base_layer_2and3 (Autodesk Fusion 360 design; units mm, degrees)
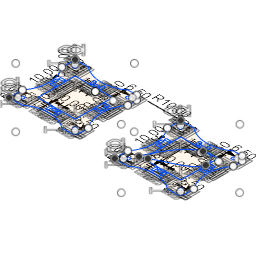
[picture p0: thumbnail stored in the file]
sketch "Sketch1" plane through (0, 0, 0) normal (0, 1, 0) x axis (1, 0, 0)
  line L1 (-53.5322, -77.3934) -> (31.4678, -77.3934)
  line L2 (-53.5322, 7.6066) -> (-53.5322, -77.3934)
  line L3 (31.4678, -77.3934) -> (31.4678, 7.6066)
  line L4 (37.4678, 2.6066) -> (40.4678, 2.6066)
  line L5 (63.9678, 9.8155) -> (63.9678, 30.1039)
  line L6 (-86.0322, -99.8934) -> (-86.0322, -79.8934)
  line L7 (63.9678, -79.8934) -> (63.9678, -99.8934)
  line L8 (53.9678, -109.8934) -> (33.9678, -109.8934)
  line L9 (-76.0322, -109.8934) -> (-56.0322, -109.8934)
  line L10 (-86.0322, 10.1066) -> (-86.0322, 30.1026)
  line L11 (53.9691, 40.1039) -> (33.9678, 40.1066)
  line L12 (-76.0322, 40.1026) -> (-56.0322, 40.1026)
  curve K1 (-62.3587, -78.4407) -> (-62.3587, -78.4407)
  line L13 (33.4678, -36.6974) -> (44.9678, -36.6974)
  line L14 (33.4678, -31.6974) -> (33.4678, -36.6974)
  line L15 (44.9678, -31.6974) -> (33.4678, -31.6974)
  line L16 (44.9678, -36.6974) -> (44.9678, -31.6974)
  line L17 (33.4678, -16.6974) -> (44.9678, -16.6974)
  line L18 (33.4678, -11.6974) -> (33.4678, -16.6974)
  line L19 (44.9678, -11.6974) -> (33.4678, -11.6974)
  line L20 (44.9678, -16.6974) -> (44.9678, -11.6974)
  line L21 (-2.5269, 20.8155) -> (2.4731, 20.8155)
  line L22 (-2.5269, 9.3155) -> (-2.5269, 20.8155)
  line L23 (2.4731, 9.3155) -> (-2.5269, 9.3155)
  line L24 (2.4731, 20.8155) -> (2.4731, 9.3155)
  line L25 (-22.5269, 20.8155) -> (-17.5269, 20.8155)
  line L26 (-22.5269, 9.3155) -> (-22.5269, 20.8155)
  line L27 (-17.5269, 9.3155) -> (-22.5269, 9.3155)
  line L28 (-17.5269, 20.8155) -> (-17.5269, 9.3155)
  line L29 (-55.5322, -11.6974) -> (-67.0322, -11.6974)
  line L30 (-55.5322, -16.6974) -> (-55.5322, -11.6974)
  line L31 (-67.0322, -16.6974) -> (-55.5322, -16.6974)
  line L32 (-67.0322, -11.6974) -> (-67.0322, -16.6974)
  line L33 (-55.5322, -31.6974) -> (-67.0322, -31.6974)
  line L34 (-55.5322, -36.6974) -> (-55.5322, -31.6974)
  line L35 (-67.0322, -36.6974) -> (-55.5322, -36.6974)
  line L36 (-67.0322, -31.6974) -> (-67.0322, -36.6974)
  line L37 (-17.5269, -90.8934) -> (-22.5269, -90.8934)
  line L38 (-17.5269, -79.3934) -> (-17.5269, -90.8934)
  line L39 (-22.5269, -79.3934) -> (-17.5269, -79.3934)
  line L40 (-22.5269, -90.8934) -> (-22.5269, -79.3934)
  line L41 (2.4731, -90.8934) -> (-2.5269, -90.8934)
  line L42 (2.4731, -79.3934) -> (2.4731, -90.8934)
  line L43 (-2.5269, -79.3934) -> (2.4731, -79.3934)
  line L44 (-2.5269, -90.8934) -> (-2.5269, -79.3934)
  line L45 (-53.5322, 7.6066) -> (31.4678, 7.6066)
  line L46 (45.4678, 22.1046) -> (45.4678, 28.6046)
  line L47 (-64, -19) -> (-69, -19)
  line L48 (-15, 15) -> (-5, 15)
  line L49 (-15, 10) -> (-15, 15)
  line L50 (-67.53, -91.393) -> (-67.53, -97.893)
  line L51 (45.9678, -98.3934) -> (45.9678, -91.8934)
  line L52 (-15, -85) -> (-5, -85)
  line L53 (45.4678, 28.6046) -> (51.9678, 28.6046)
  line L54 (46.4751, -29) -> (46.4751, -19)
  line L55 (-74.5, 21.5) -> (-74.5, 28)
  line L56 (-74.5, 28) -> (-68, 28)
  line L57 (41.4751, -29) -> (46.4751, -29)
  line L58 (51.9678, 22.1046) -> (45.4678, 22.1046)
  line L59 (-74.03, -97.893) -> (-74.03, -91.393)
  line L60 (-5, 15) -> (-5, 10)
  line L61 (-68, 28) -> (-68, 21.5)
  line L62 (41.4751, -19) -> (41.4751, -29)
  line L63 (-64, -29) -> (-64, -19)
  line L64 (51.9678, 28.6046) -> (51.9678, 22.1046)
  line L65 (46.4751, -19) -> (41.4751, -19)
  line L66 (-68, 21.5) -> (-74.5, 21.5)
  line L67 (-67.53, -97.893) -> (-74.03, -97.893)
  line L68 (-69, -19) -> (-69, -29)
  line L69 (-5, 10) -> (-15, 10)
  line L70 (52.4678, -98.3934) -> (45.9678, -98.3934)
  line L71 (-5, -80) -> (-15, -80)
  line L72 (-69, -29) -> (-64, -29)
  line L73 (45.9678, -91.8934) -> (52.4678, -91.8934)
  line L74 (-15, -80) -> (-15, -85)
  line L75 (52.4678, -91.8934) -> (52.4678, -98.3934)
  line L76 (-74.03, -91.393) -> (-67.53, -91.393)
  line L77 (-5, -85) -> (-5, -80)
  line L78 (-186.0322, -109.8934) -> (-206.0322, -109.8934)
  line L79 (-295.5322, -31.6974) -> (-307.0322, -31.6974)
  line L80 (-262.5269, -90.8934) -> (-262.5269, -79.3934)
  line L81 (-187.5322, -91.8934) -> (-187.5322, -98.3934)
  line L82 (-262.5269, -79.3934) -> (-257.5269, -79.3934)
  line L83 (-307.0322, -31.6974) -> (-307.0322, -36.6974)
  line L84 (-187.5322, -98.3934) -> (-194.0322, -98.3934)
  line L85 (-257.5269, -90.8934) -> (-262.5269, -90.8934)
  line L86 (-242.5269, -79.3934) -> (-237.5269, -79.3934)
  line L87 (-237.5269, -90.8934) -> (-242.5269, -90.8934)
  line L88 (-194.0322, -91.8934) -> (-187.5322, -91.8934)
  line L89 (-242.5269, -90.8934) -> (-242.5269, -79.3934)
  line L90 (-307.0322, -16.6974) -> (-295.5322, -16.6974)
  line L91 (-307.0322, -11.6974) -> (-307.0322, -16.6974)
  line L92 (-309, -19) -> (-309, -29)
  line L93 (-255, 10) -> (-255, 15)
  line L94 (-316.0322, -109.8934) -> (-296.0322, -109.8934)
  line L95 (-245, 15) -> (-245, 10)
  line L96 (-245, 10) -> (-255, 10)
  line L97 (-176.0322, 9.8155) -> (-176.0322, 30.1039)
  line L98 (-314.5, 28) -> (-308, 28)
  line L99 (-308, 28) -> (-308, 21.5)
  line L100 (-293.5322, 7.6066) -> (-293.5322, -77.3934)
  line L101 (-257.5269, 9.3155) -> (-262.5269, 9.3155)
  line L102 (-262.5269, 20.8155) -> (-257.5269, 20.8155)
  line L103 (-326.0322, -99.8934) -> (-326.0322, -79.8934)
  line L104 (-237.5269, 9.3155) -> (-242.5269, 9.3155)
  line L105 (-242.5269, 9.3155) -> (-242.5269, 20.8155)
  line L106 (-255, 15) -> (-245, 15)
  line L107 (-262.5269, 9.3155) -> (-262.5269, 20.8155)
  line L108 (-304, -19) -> (-309, -19)
  line L109 (-314.5, 21.5) -> (-314.5, 28)
  line L110 (-208.5322, -77.3934) -> (-208.5322, 7.6066)
  line L111 (-308, 21.5) -> (-314.5, 21.5)
  line L112 (-257.5269, 20.8155) -> (-257.5269, 9.3155)
  line L113 (-304, -29) -> (-304, -19)
  line L114 (-307.0322, -36.6974) -> (-295.5322, -36.6974)
  line L115 (-186.0309, 40.1039) -> (-206.0322, 40.1066)
  line L116 (-195.0322, -11.6974) -> (-206.5322, -11.6974)
  line L117 (-193.5249, -19) -> (-198.5249, -19)
  line L118 (-206.5322, -11.6974) -> (-206.5322, -16.6974)
  line L119 (-195.0322, -16.6974) -> (-195.0322, -11.6974)
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  point P4 (-53.5322, -77.3934)
  point P5 (-53.5322, 7.6066)
  point P97 (-5, -80)
  point P110 (-15, -80)
  point P106 (-15, -85)
  point P102 (-5, 10)
  point P105 (-15, 10)
  point P89 (-69, -19)
  point P96 (-69, -29)
  point P99 (46.4751, -19)
  point P103 (41.4751, -19)
  point P109 (41.4751, -29)
  point P75 (-74.03, -91.393)
  point P80 (-74.03, -97.893)
  point P76 (-67.53, -97.893)
  point P120 (-293.5322, 7.6066)
  point P121 (-293.5322, -77.3934)
  point P187 (-255, -80)
  point P191 (-245, -80)
  point P203 (-255, -85)
  point P200 (-245, 10)
  point P201 (-255, 10)
  point P132 (-309, -19)
  point P204 (-309, -29)
  point P195 (-193.5249, -19)
  point P206 (-198.5249, -19)
  point P194 (-198.5249, -29)
  point P170 (-314.03, -97.893)
  point P216 (-314.03, -91.393)
  point P213 (-307.53, -97.893)
  dimension "d162" distance P4 P5 = 85
  dimension "d502" radius = 10
  dimension "d694" distance L22 L28 = 15
  dimension "d743" distance P97 P110 = 10
  dimension "d744" distance P106 P110 = 5
  dimension "d745" distance P102 P105 = 10
  dimension "d746" distance P89 P96 = 10
  dimension "d747" distance P99 P103 = 5
  dimension "d748" distance P103 P109 = 10
  dimension "d750" distance P75 P80 = 6.5
  dimension "d751" distance P76 P80 = 6.5
  dimension "d752" distance L56 L66 = 6.5
  dimension "d753" distance L55 L61 = 6.5
  dimension "d754" distance L53 L58 = 6.5
  dimension "d755" distance L46 L64 = 6.5
  dimension "d756" distance L51 L75 = 6.5
  dimension "d757" distance L70 L73 = 6.5
  dimension "d768" distance P120 P121 = 85
  dimension "d769" radius = 10
  dimension "d770" distance L105 L112 = 15
  dimension "d771" distance P187 P191 = 10
  dimension "d772" distance P187 P203 = 5
  dimension "d773" distance P200 P201 = 10
  dimension "d774" distance P132 P204 = 10
  dimension "d775" distance P195 P206 = 5
  dimension "d776" distance P194 P206 = 10
  dimension "d777" distance P170 P216 = 6.5
  dimension "d778" distance P170 P213 = 6.5
  dimension "d779" distance L98 L111 = 6.5
  dimension "d780" distance L99 L109 = 6.5
  dimension "d781" distance = 6.5
  dimension "d782" distance = 6.5
  dimension "d783" distance = 6.5
  dimension "d784" distance L84 L88 = 6.5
